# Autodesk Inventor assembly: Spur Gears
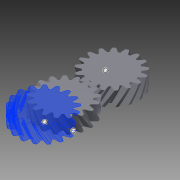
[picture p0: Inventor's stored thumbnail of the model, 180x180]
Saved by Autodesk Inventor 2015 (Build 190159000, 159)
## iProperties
Created: 2014-06
Part Number: Spur Gears
Document SubType Name: Assembly
Designer: User
Categories: <?xml version="1.0" encoding="UTF-16"?> <MemberInstance><Categories><FamilyTemplate/><ParamToTemplateMap><ParamToTemplate><ParamToTemplate CategoryParameter="//
ClientObjectVersion: 1
Author: User
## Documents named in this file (3)
- Z:\CAD Files\Belt_Extruder\Helical_Gear_Assembly\Design Accelerator\Spur Gears1.iam
- Z:\CAD Files\Belt_Extruder\Helical_Gear_Assembly\Design Accelerator\Spur Gear11.ipt
- Z:\CAD Files\Belt_Extruder\Helical_Gear_Assembly\Design Accelerator\Spur Gear21.ipt
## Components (2 placed, 2 different names)
1. Spur Gear1:1 — Rotation:1
2. Spur Gear2:1 — Rotation:1
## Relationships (1: RelateRotation 1)
- Rotation:1 [RelateRotation]: Spur Gear1:1 ↔ Spur Gear2:1
